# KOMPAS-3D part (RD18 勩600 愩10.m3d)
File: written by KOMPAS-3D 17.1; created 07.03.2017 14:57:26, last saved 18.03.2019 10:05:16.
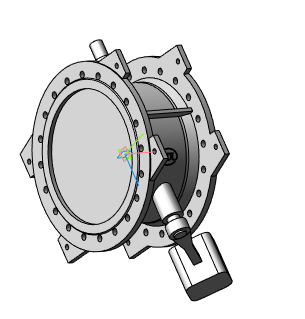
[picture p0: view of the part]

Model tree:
1. Операция без истории:2  (labels: Сталь 20  ГОСТ 1050-88)

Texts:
  RD18 Ду100 Ру16
  RD18 Ду150 Ру16
  RD18 Ду200 Ру16
  RD18 Ду250 Ру16
  RD18 Ду300 Ру16
  RD18 Ду350 Ру16
  RD18 Ду400 Ру10
  RD18 Ду400 Ру16
  RD18 Ду450 Ру10
  RD18 Ду450 Ру16
  RD18 Ду500 Ру10
  RD18 Ду500 Ру16
  RD18 Ду600 Ру10
  RD18 Ду600 Ру16
  RD18 Ду700 Ру10
  RD18 Ду700 Ру16
  RD18 Ду800 Ру10
  RD18 Ду800 Ру16
  RD18 Ду900 Ру10
  RD18 Ду900 Ру16
  RD18 Ду1000 Ру10
  RD18 Ду1000 Ру16
  RD18 Ду1200 Ру16
  RD18 Ду1400 Ру16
